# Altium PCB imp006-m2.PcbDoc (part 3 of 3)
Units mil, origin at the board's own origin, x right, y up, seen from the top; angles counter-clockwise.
Board outline 1181.1 x 1515.75 mil, 4 copper layers (Top Layer, Signal Layer 1, Signal Layer 2, Bottom Layer), stack 31.759 mil thick; 78 components, 116 nets, 508 pads, 482 vias.
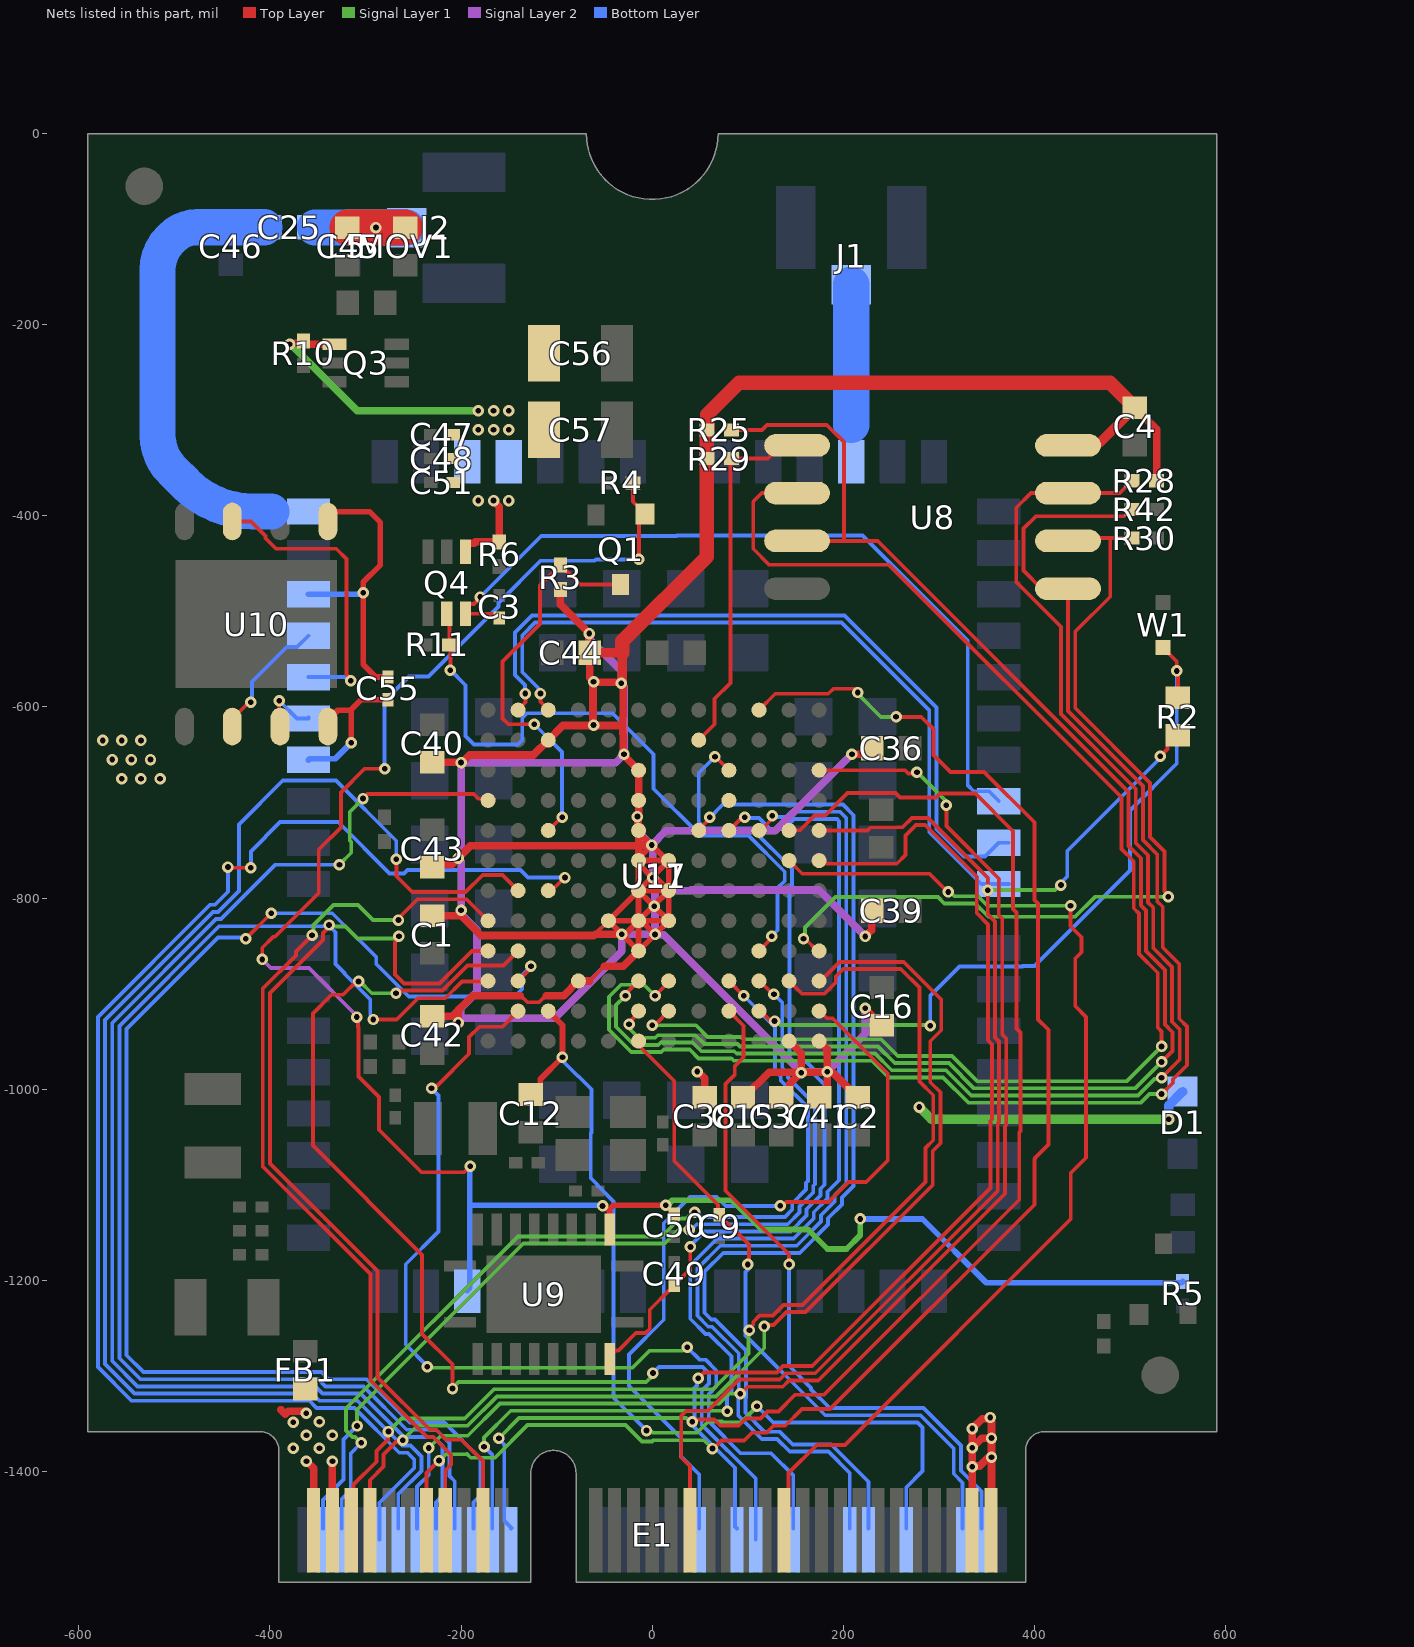
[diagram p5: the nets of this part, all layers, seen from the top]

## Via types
v1: diameter 12, hole 6, Top Layer to Bottom Layer, tented both sides, 300 vias
v2: diameter 16, hole 8, Top Layer to Bottom Layer, tented both sides, 95 vias
v3: diameter 12, hole 6, Top Layer to Signal Layer 1, tented both sides, 86 vias
v4: diameter 141.73, hole 137.8, Top Layer to Bottom Layer, tented both sides, 1 vias

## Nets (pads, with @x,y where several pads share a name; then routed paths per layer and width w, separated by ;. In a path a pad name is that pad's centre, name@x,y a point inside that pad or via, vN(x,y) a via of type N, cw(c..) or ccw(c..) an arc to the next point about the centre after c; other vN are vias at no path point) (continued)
PINW: E1.73 U17.J2 | length 724.1
  Top Layer w4: U17.J2@80.2,-918.19 95.6,-933.59 95.6,-966.46 86.43,-975.63 86.43,-984.69 79.69,-991.43 76.7,-994.41 76.7,-1106.17 143.19,-1172.65 v1(143.19,-1183.26)
  Bottom Layer w4: v1(143.19,-1183.26) 143.19,-1289.37 166.27,-1312.46 166.27,-1314.18 185.78,-1333.69 283.9,-1333.69 322.96,-1372.75 322.96,-1399.22 344.49,-1420.75 E1.73@344.49,-1459.65
PINXA: E1.8 U17.M3 | length 1137.2
  Top Layer w4: E1.8@-295.28,-1449.8 -295.28,-1409.09 -281.04,-1394.86 -281.04,-1382.1 -267.66,-1368.72 -262.53,-1368.72 v3(-261,-1367.19) ; v3(117.16,-1248.19) 118.69,-1246.66 126.96,-1246.66 140.42,-1233.19 160.35,-1233.19 293.5,-1100.04 293.5,-1064.43 301.5,-1056.43 301.5,-1003.19 290.96,-992.65 290.96,-949.84 302.5,-938.3 302.5,-906.05 263.14,-866.69 196.03,-866.69 176.03,-886.69 U17.M3@174.69,-886.69
  Signal Layer 1 w4: v3(-261,-1367.19) -245.93,-1352.11 -193.15,-1352.11 -162.49,-1321.46 66.77,-1321.46 117.16,-1271.06 v3(117.16,-1248.19)
PINXB: E1.6 U17.L3 | length 1171.6
  Top Layer w4: E1.6@-314.96,-1449.8 -314.96,-1428.34 -312.49,-1425.87 -312.49,-1413.67 -288.54,-1389.72 -288.54,-1378.47 -276.62,-1366.54 -276.62,-1358.81 v3(-276,-1358.19) ; v3(101.66,-1252.19) 101.66,-1250.02 105.66,-1246.02 105.66,-1243.43 112.4,-1236.69 126.32,-1236.69 137.32,-1225.69 157.24,-1225.69 286,-1096.93 286,-1061.32 294,-1053.32 294,-1006.3 279.5,-991.8 279.5,-893.66 260.03,-874.19 199.8,-874.19 192.07,-881.93 192.07,-888.23 180.22,-900.07 156.56,-900.07 U17.L3@143.19,-886.69
  Signal Layer 1 w4: v3(-276,-1358.19) -262.43,-1344.61 -196.25,-1344.61 -165.6,-1313.96 63.66,-1313.96 100.9,-1276.72 100.9,-1252.95 v3(101.66,-1252.19)
PINXC: E1.3 U17.K3 | length 961.9
  Top Layer w4: U17.K3@111.69,-886.69 112.54,-886.69 126.49,-900.65 v1(127.34,-900.65)
  Signal Layer 1 w4: v1(-308.9,-1352.36) -308.9,-1335.36 -135,-1161.46 13.1,-1161.46 27.7,-1146.86 v1(38.83,-1146.86)
  Bottom Layer w4: E1.3@-344.49,-1459.65 -344.49,-1429.72 -323.04,-1408.27 -323.04,-1366.5 v1(-308.9,-1352.36) ; v1(38.83,-1146.86) 40.99,-1146.86 46.66,-1141.19 141.87,-1141.19 154,-1129.06 154,-1122.51 168.5,-1108.01 168.5,-1101 170.47,-1099.03 170.47,-1016.06 142.03,-987.62 142.03,-983.48 136.09,-977.54 136.09,-969.79 136.09,-909.36 v1(127.34,-900.65)
PINXD: E1.5 U17.J3 | length 979.6
  Top Layer w4: U17.J3@80.2,-886.69 95.62,-902.12 v1(95.71,-902.12)
  Signal Layer 1 w4: v1(-304.53,-1369.96) -304.77,-1369.96 -310.87,-1363.86 -313.66,-1363.86 -320.4,-1357.12 -320.4,-1333.86 -140.5,-1153.96 9.99,-1153.96 28.59,-1135.36 35.93,-1135.36 42.6,-1128.69 v1(44.3,-1128.69)
  Bottom Layer w4: E1.5@-324.8,-1459.65 -324.8,-1428.46 -315.54,-1419.2 -315.54,-1380.97 v1(-304.53,-1369.96) ; v1@45.11,-1127.88 50.92,-1133.69 138.76,-1133.69 146.5,-1125.95 146.5,-1119.41 161,-1104.91 161,-1097.89 162.97,-1095.92 162.97,-1019.17 134.53,-990.73 134.53,-986.58 128.59,-980.64 128.59,-935 v1(95.71,-902.12)
PinXE: E1.9 U17.C6 | length 1485.3
  Top Layer w4: v1(-443.95,-767.5) -443.25,-768.19 v1(-420,-768.19) ; U17.C6@-108.78,-792.2 -105.6,-792.2 -101.57,-788.17 -101.19,-788.17 -91.51,-778.5 v1(-91.39,-778.5)
  Bottom Layer w4: v1(-443.95,-767.5) -443.95,-793.4 -457.53,-806.98 -462.59,-806.98 -580,-924.39 -580,-1290.73 -544.73,-1326 -358.65,-1326 -351.15,-1333.5 -311.49,-1333.5 -264.66,-1380.34 -256.16,-1380.34 -249.04,-1387.45 -249.04,-1396.22 -285.43,-1432.61 E1.9@-285.43,-1471.46 ; v1(-420,-768.19) -420,-751.04 -389.44,-720.48 -328.48,-720.48 -274.77,-774.19 -259.74,-774.19 -256.23,-770.68 -137.69,-770.68 -129.97,-778.41 -91.48,-778.41 v1(-91.39,-778.5)
PinXF: E1.11 U17.B6 | length 1477.4
  Top Layer w4: v1(-267.84,-759.35) -267.61,-759.59 -267.61,-777.18 -251.09,-793.69 -195.25,-793.69 -177.31,-775.75 -156.73,-775.75 U17.B6@-140.28,-792.2
  Bottom Layer w4: v1(-267.84,-759.35) -267.84,-740.03 -330.87,-677.01 -386.55,-677.01 -432.45,-722.91 -432.45,-792.51 -454.42,-814.48 -459.48,-814.48 -572.5,-927.5 -572.5,-1287.62 -541.62,-1318.5 -355.55,-1318.5 -348.05,-1326 -308.39,-1326 -261.55,-1372.84 -253.05,-1372.84 -241.54,-1384.34 -241.54,-1399.33 -265.75,-1423.53 E1.11@-265.75,-1459.65
PinXG: E1.13 U17.M10 | length 1384.9
  Top Layer w4: v3(92.24,-1318.69) 99.67,-1311.26 136.6,-1311.26 143.17,-1304.69 173.7,-1304.69 369,-1109.39 369,-1039.11 370.5,-1037.61 370.5,-946.79 366.29,-942.58 366.29,-821.31 362.5,-817.52 362.5,-779.18 307.75,-724.43 v3(307.75,-702.8) ; U17.M10@174.69,-666.22 264.33,-666.22 267.87,-669.76 270.66,-669.76 270.7,-669.72 275.47,-669.72 v3(277,-668.19)
  Signal Layer 1 w4: v1(-233.83,-1375.35) -221.02,-1362.54 -192.96,-1362.54 -159.38,-1328.96 69.88,-1328.96 80.14,-1318.69 89.24,-1318.69 v3@89.66,-1319.1 ; v3(277,-668.19) 306.22,-697.41 306.22,-701.27 v3(307.75,-702.8)
  Bottom Layer w4: E1.13@-246.06,-1459.65 -246.06,-1415.77 -233.88,-1403.59 -233.88,-1375.4 v1(-233.83,-1375.35)
PinXH: E1.15 U17.A9 | length 1352.7
  Top Layer w4: v3(-302.64,-695.87) -305.05,-693.47 -300.73,-693.47 -298.26,-691 -186.8,-691 -181.74,-696.06 -173.43,-696.06 U17.A9@-171.77,-697.72
  Signal Layer 1 w4: v1(-327.3,-765) -314.89,-752.59 -314.89,-741.38 -316.5,-739.76 -316.5,-709.73 v3(-302.64,-695.87)
  Bottom Layer w4: v1(-327.3,-765) -394.33,-765 -451.31,-821.98 -456.37,-821.98 -565,-930.61 -565,-1284.52 -538.52,-1311 -352.44,-1311 -344.94,-1318.5 -305.28,-1318.5 -259.92,-1363.85 -229.07,-1363.85 -219.54,-1373.38 -219.54,-1425.25 -226.38,-1432.09 E1.15@-226.38,-1459.65
PinXJ: E1.52 U17.L7 | length 1116.5
  Top Layer w4: E1.52@137.8,-1449.8 142.69,-1444.91 142.69,-1401.63 172.13,-1372.19 201.66,-1372.19 438,-1135.85 438,-1087.62 454,-1071.62 454,-924.23 442.7,-912.92 442.7,-863.21 449.29,-856.62 449.29,-840.88 437.79,-829.38 v3(437.79,-807.95) ; U17.L7@143.19,-760.71 157.02,-774.54 290.3,-774.54 309.23,-793.48 v3(309.8,-793.48)
  Signal Layer 1 w4: v3(309.8,-793.48) 311.61,-793.48 316.14,-798.01 340.88,-798.01 350.82,-807.95 v3(437.79,-807.95)
PinXK: E1.47 U17.M7 | length 1116.2
  Top Layer w4: v1(48.03,-1302.33) 48.27,-1302.33 54.34,-1296.26 130.39,-1296.26 136.96,-1289.69 167.49,-1289.69 354,-1103.18 354,-1032.89 355.5,-1031.39 355.5,-953 351.29,-948.79 351.29,-827.52 339.5,-815.73 339.5,-777.39 285.61,-723.5 276.03,-723.5 265.16,-734.38 265.16,-754.8 255.91,-764.05 182.9,-764.05 181.8,-762.96 176.93,-762.96 U17.M7@174.69,-760.71
  Bottom Layer w4: v1(48.03,-1302.33) 47.86,-1302.33 46.81,-1303.38 46.81,-1310.08 44.22,-1312.67 44.22,-1353.79 86.46,-1396.03 86.46,-1457.52 E1.47@88.58,-1459.65
PinXL: U17.J9
PinXN: E1.43 U17.M2 | length 824.4
  Top Layer w4: v1(134,-1122) 135.98,-1122 136.98,-1121 137.16,-1121.19 140.43,-1117.92 184.58,-1117.92 205.4,-1097.1 223.97,-1097.1 246.52,-1074.55 246.52,-983.56 188.66,-925.71 182.9,-925.71 175.38,-918.19 U17.M2@174.69,-918.19
  Bottom Layer w4: E1.43@49.21,-1459.65 49.21,-1403.2 30.28,-1384.27 30.28,-1364.94 -24.29,-1310.38 -24.29,-1277.49 12.05,-1241.15 12.05,-1140.18 39.58,-1112.65 67.55,-1112.65 76.9,-1122 v1(134,-1122)
PinXP: E1.49 U17.B4 | length 1188
  Top Layer w4: v3(-307.33,-887.2) -309.5,-887.2 -323.42,-901.12 -335.43,-901.12 -355,-920.69 -355,-1059 -240.75,-1173.25 -240.75,-1256.06 -209,-1287.81 v3(-209,-1313.19) ; v3(-268.11,-899.56) -265.24,-896.69 -219.5,-896.69 -193.27,-870.46 -155.54,-870.46 U17.B4@-140.28,-855.2
  Signal Layer 1 w4: v3(-307.33,-887.2) -305.91,-887.2 -293.55,-899.56 v3(-268.11,-899.56) ; v3(-209,-1313.19) -209,-1312.8 -202.66,-1306.46 -6.27,-1306.46 0.74,-1299.45 v1(0.74,-1297.02)
  Bottom Layer w4: v1(0.74,-1297.02) 7.08,-1290.69 52.76,-1290.69 59.53,-1297.46 59.53,-1307.97 51.72,-1315.77 51.72,-1350.69 108.27,-1407.23 E1.49@108.27,-1471.46
PinXQ: E1.19 U17.B3 | length 1390.1
  Top Layer w4: v1(-425.42,-842.6) v1(-398.62,-815.81) ; U17.B3@-140.28,-886.69 -127.24,-873.66 -127.24,-871.65 v1(-126.89,-871.29)
  Bottom Layer w4: v1(-425.42,-842.6) -426.82,-841.19 -454.37,-841.19 -550,-936.82 -550,-1278.3 -532.3,-1296 -346.23,-1296 -338.73,-1303.5 -299.07,-1303.5 -253.71,-1348.85 -217.44,-1348.85 -179.71,-1386.59 -179.71,-1424.85 -182.06,-1427.2 -182.12,-1427.2 -187.01,-1432.09 E1.19@-187.01,-1459.65 ; v1(-398.62,-815.81) -334.79,-815.81 -288.85,-861.74 -288.85,-868.89 -254.76,-902.98 -143.91,-902.98 -136.27,-895.35 -136.27,-880.68 v1(-126.89,-871.29)
PinXR: E1.17 U17.A3 | length 1337.9
  Top Layer w4: v1(-292.04,-927) -267.31,-927 -245.02,-904.7 -216.51,-904.7 -199,-887.19 -172.27,-887.19 U17.A3@-171.77,-886.69
  Bottom Layer w4: v1(-292.04,-927) -292.04,-924.84 -295,-921.88 -295,-906.13 -322,-879.13 -322,-878.48 -331.5,-868.98 -331.5,-835.66 -337.68,-829.48 -453.27,-829.48 -557.5,-933.71 -557.5,-1281.41 -535.41,-1303.5 -349.33,-1303.5 -341.83,-1311 -302.17,-1311 -256.82,-1356.35 -225.96,-1356.35 -212.04,-1370.28 -212.04,-1404.77 -206.69,-1410.12 E1.17@-206.69,-1459.65
PinXS: E1.53 U17.B2 | length 998.1
  Top Layer w4: v1(-230.91,-998.97) -228.74,-998.97 -225.82,-996.05 -224.86,-996.05 -191.68,-962.87 -191.68,-945.32 -180.89,-934.53 -156.62,-934.53 U17.B2@-140.28,-918.19
  Signal Layer 1 w4: v1(-235.54,-1290.38) -234.46,-1291.46 -20.57,-1291.46 -2.65,-1273.54 32.01,-1273.54 35.51,-1270.04 v1(36.71,-1270.04)
  Bottom Layer w4: v1(-235.54,-1290.38) -235.54,-1289.59 -257.87,-1267.25 -257.87,-1183.06 -223.5,-1148.69 -223.5,-1006.38 v1(-230.91,-998.97) ; v1(36.71,-1270.04) 49.63,-1282.96 55.64,-1282.96 67.03,-1294.35 67.03,-1311.07 59.22,-1318.88 59.22,-1347.58 92.61,-1380.96 124.49,-1380.96 147.64,-1404.11 E1.53@147.64,-1459.65
PinXT: E1.23 U17.L8 | length 1409.2
  Top Layer w4: 48.34,-1345.69 64.97,-1345.69 71.24,-1351.96 90.58,-1351.96 98.06,-1344.48 113.19,-1344.48 120.61,-1337.07 132.01,-1337.07 149.38,-1319.69 179.91,-1319.69 384,-1115.6 384,-1045.32 385.5,-1043.82 385.5,-940.58 381.29,-936.37 381.29,-815.09 377.5,-811.3 377.5,-729.99 338.2,-690.69 301.24,-690.69 297.24,-694.69 259.27,-694.69 254.64,-690.06 204.39,-690.06 181,-713.46 169.97,-713.46 154.51,-728.92 143.49,-728.92 U17.L8@143.19,-729.21
  Signal Layer 1 w4: v1(-160.46,-1365.11) -139.3,-1343.96 35.66,-1343.96 39.66,-1347.96 v3(42,-1347.96)
  Bottom Layer w4: v1(-160.46,-1365.11) -160.46,-1365.93 -154.93,-1371.46 -154.93,-1451.41 -147.17,-1459.18 E1.23@-147.64,-1459.65
PinXU: E1.59 U17.K8 | length 1061.6
  Top Layer w4: U17.K8@111.69,-729.21 113.31,-729.21 123.99,-718.53 123.99,-715.29 v1(125.52,-713.76)
  Bottom Layer w4: v1(125.52,-713.76) 127.89,-713.76 129.14,-715 139.95,-715 145.26,-709.69 196.38,-709.69 203.02,-716.33 203.02,-1098.3 191,-1110.32 191,-1117.33 176.5,-1131.83 176.5,-1138.38 151.19,-1163.69 71.19,-1163.69 47.28,-1187.6 47.28,-1237.04 58.69,-1248.46 62.65,-1248.46 90.5,-1276.31 90.5,-1319.43 90.03,-1319.89 90.03,-1341.46 114.54,-1365.96 130.7,-1365.96 143.93,-1379.19 184.26,-1379.19 206.69,-1401.62 E1.59@206.69,-1459.65
PinXV: E1.21 U17.J8 | length 1239.5
  Top Layer w4: U17.J8@80.2,-729.21 v1@91.74,-717.67
  Signal Layer 1 w4: v1(-176,-1374.04) -176,-1364.39 -148.07,-1336.46 76.45,-1336.46 76.86,-1336.87 v1(78.53,-1336.87)
  Bottom Layer w4: v1@-174.47,-1375.57 -167.32,-1382.71 E1.21@-167.32,-1459.65 ; v1(78.53,-1336.87) 78.22,-1336.57 78.22,-1321.09 83,-1316.32 83,-1279.41 59.54,-1255.96 55.58,-1255.96 39.78,-1240.15 39.78,-1184.5 68.08,-1156.19 148.08,-1156.19 169,-1135.27 169,-1128.73 183.5,-1114.23 183.5,-1107.21 195.52,-1095.19 195.52,-719.54 193.18,-717.19 148.37,-717.19 137.88,-727.69 123.19,-727.69 111.69,-716.19 97.42,-716.19 v1(96.7,-715.47)
PinXW: E1.61 U17.H8 | length 1143.6
  Top Layer w4: U17.H8@48.7,-729.21 48.7,-728.11 60.23,-716.57 v1(60.23,-715.47)
  Bottom Layer w4: v1(60.23,-715.47) 60.48,-715.47 73.75,-702.19 199.49,-702.19 210.52,-713.22 210.52,-1101.41 198.5,-1113.43 198.5,-1120.44 184,-1134.94 184,-1141.49 154.3,-1171.19 74.3,-1171.19 54.78,-1190.71 54.78,-1233.94 61.79,-1240.96 65.75,-1240.96 98,-1273.2 98,-1322.54 97.53,-1323 97.53,-1338.35 117.65,-1358.46 133.81,-1358.46 147.03,-1371.69 187.37,-1371.69 226.38,-1410.7 E1.61@226.38,-1459.65
PinYA: E1.20 U17.A4 | length 989.4
  Top Layer w4: v3(-338.14,-828.12) -338.14,-830.29 -344.46,-836.61 -344.46,-843.72 -400,-899.26 -400,-1077.79 -287.43,-1190.35 -287.43,-1301.45 -232.52,-1356.35 -225.96,-1356.35 -215.63,-1366.69 -199.61,-1366.69 -177.17,-1389.13 E1.20@-177.17,-1449.8 ; v3(-265,-840) -265,-842.16 -269,-846.16 -269,-879.86 -259.67,-889.19 -222.61,-889.19 -188.61,-855.2 U17.A4@-171.77,-855.2
  Signal Layer 1 w4: v3(-338.14,-828.12) -336.72,-829.53 -321.06,-829.53 -308.41,-842.19 -269.35,-842.19 -267.16,-840 v3(-265,-840)
PinYB: E1.16 U17.A5 | length 960.8
  Top Layer w4: v3(-355.96,-838.95) -372.91,-855.9 -372.91,-859.88 -407.5,-894.47 -407.5,-1080.89 -294.93,-1193.46 -294.93,-1304.55 -235.63,-1363.85 -229.07,-1363.85 -210.5,-1382.43 -210.5,-1392.95 -216.54,-1398.99 E1.16@-216.54,-1461.61 ; v3(-265.54,-823) -265.54,-821.02 -245.71,-801.19 -194.28,-801.19 U17.A5@-171.77,-823.7
  Signal Layer 1 w4: v3(-355.96,-838.95) -354.43,-837.42 -354.43,-828.15 -333.48,-807.19 -307.92,-807.19 -292.11,-823 v3(-265.54,-823)
PinYC: E1.42 R2.2 U17.M8 | length 1368.5
  Top Layer w4: E1.42@39.37,-1449.8 39.37,-1394.17 30.28,-1385.08 30.28,-1341.91 35.73,-1336.46 58.21,-1336.46 90.91,-1303.76 133.5,-1303.76 140.06,-1297.19 170.59,-1297.19 361.5,-1106.28 361.5,-1036 363,-1034.5 363,-949.9 358.79,-945.69 358.79,-824.41 351,-816.62 351,-778.28 288.72,-716 271.73,-716 261.88,-725.85 228.72,-725.85 225.36,-729.21 U17.M8@174.69,-729.21 ; v1(531.63,-651.54) 539.2,-643.96 539.2,-639.5 549.02,-629.68 R2.2@550,-629.68
  Signal Layer 1 w4: v3(351,-791.87) 351.39,-791.48 421.29,-791.48 426.47,-786.3 v1(427.63,-786.3)
  Bottom Layer w4: v1(427.63,-786.3) 427.63,-784.13 434.25,-777.51 434.25,-750.76 531.63,-653.38 v1(531.63,-651.54)
PinYD: E1.14 U17.K12 | length 1619
  Top Layer w4: E1.14@-236.22,-1461.61 -236.22,-1401.62 v3(-223.1,-1388.5) ; v3@63,-1376.97 v3(63,-1376) ; v3@63.03,-1377 72.63,-1367.39 96.36,-1367.39 104.27,-1359.48 119.41,-1359.48 126.82,-1352.07 139.22,-1352.07 156.6,-1334.69 186.13,-1334.69 400,-1120.82 400,-1073.19 400.5,-1072.69 400.5,-1072.08 405.2,-1067.39 405.2,-1067.26 414.5,-1057.95 414.5,-937.76 403.79,-927.05 403.79,-805.77 400,-801.98 400,-720.67 347.28,-667.96 312.02,-667.96 294.32,-650.25 294.32,-623.18 281.46,-610.33 v3(255.16,-610.33) ; U17.K12@111.69,-603.23 128.73,-586.19 184.23,-586.19 189.57,-580.85 v3@212.76,-580.85
  Signal Layer 1 w4: v3(-223.1,-1388.5) -222.79,-1388.19 -222,-1388.19 -215.77,-1381.96 -193.97,-1381.96 -193.72,-1381.71 -189.9,-1385.54 -164.62,-1385.54 -130.54,-1351.46 -28,-1351.46 -10.76,-1368.69 -0.06,-1368.69 1.44,-1367.19 53.94,-1367.19 62.75,-1376 v3(63,-1376) ; v3(215.16,-584.85) 215.16,-586.37 239.12,-610.33 v3(255.16,-610.33)
PinYK: Q1.3 R3.2 U17.C8 | length 423.1
  Top Layer w4: v1(-123.39,-618.11) -150.5,-618.11 -156.73,-611.88 -156.73,-552.48 -117.5,-513.25 -117.5,-472.66 -101.97,-457.13 -100.99,-457.13 R3.2@-96.1,-452.24 ; U17.C8@-108.78,-729.21 -95.01,-715.44 v1(-94.26,-715.44) ; R3.2@-96.1,-451.26 R3.2@-96.1,-452.24 ; Q1.3@-33.03,-471.87 -75.48,-471.87 -90.23,-457.13 -91.21,-457.13 R3.2@-96.1,-452.24
  Bottom Layer w4: v1(-123.39,-618.11) -94.26,-647.24 v1(-94.26,-715.44)
QSPI_CLK: R30.1 U8.6 U17.M4 | length 943.8
  Top Layer w4: v3(158.29,-842.48) 160.13,-842.48 172.84,-855.2 U17.M4@174.69,-855.2 ; U8.6@435.04,-426.22 438.07,-423.19 479.19,-423.19 ; R30.1@502.2,-423.19 479.19,-423.19 ; v3(540,-798.65) 540,-796.49 536,-792.49 536,-751.09 521,-736.09 521,-679.49 442.7,-601.18 442.7,-521.17 479.19,-484.68 479.19,-423.19
  Signal Layer 1 w4: v3(158.29,-842.48) 159.82,-840.95 159.82,-836 159.89,-835.92 159.89,-830.69 191.6,-798.98 299.03,-798.98 305.57,-805.51 337.77,-805.51 351.72,-819.45 442.55,-819.45 463.35,-798.65 v3(540,-798.65)
QSPI_CS: R29.2 U8.1 U17.H11 | length 384.1
  Top Layer w4: U17.H11@48.7,-634.72 65.31,-618.11 65.31,-591.33 81.81,-574.83 81.81,-340 120.84,-340 125.18,-335.66 125.18,-335.28 134.25,-326.22 U8.1@151.57,-326.22
QSPI_IO0: R42.1 U8.5 U17.G3 | length 1541.9
  Top Layer w4: v3(3,-902.19) 17.2,-887.98 U17.G3@17.2,-886.69 ; R42.1@496.33,-398.12 493.99,-400.46 401.39,-400.46 388.46,-413.39 388.46,-457.33 407.35,-476.22 U8.5@435.04,-476.22 435.2,-476.38 435.2,-604.29 513.5,-682.6 513.5,-739.19 528.5,-754.19 528.5,-803.42 534.14,-809.06 534.14,-851.49 551.5,-868.84 551.5,-926.2 559.5,-934.2 559.5,-974.86 544.63,-989.72 544.63,-993.37 v3(533,-1005) ; R42.1@496.33,-398.08 501.22,-393.19 R42.1@502.2,-393.19
  Signal Layer 1 w4: v3(3,-902.19) -8.57,-890.62 -32.76,-890.62 -45.32,-903.18 -45.32,-937.77 -21.96,-961.12 9.42,-961.12 12.05,-958.5 39.23,-958.5 48.42,-967.69 82.76,-967.69 85.26,-970.19 230.14,-970.19 247.58,-987.62 304.23,-987.62 330.64,-1014.03 511.37,-1014.03 520.4,-1005 v3(533,-1005)
QSPI_IO1: U8.2 U17.G2 | length 1461.2
  Top Layer w4: v3@3.85,-931.54 U17.G2@17.2,-918.19 ; U8.2@151.57,-376.22 114.59,-376.22 105.66,-385.15 105.66,-434.41 122.51,-451.26 247.82,-451.26 491,-694.43 491,-748.51 503.91,-761.43 503.91,-810.65 509.29,-816.03 509.29,-858.45 529,-878.16 529,-935.52 533,-939.52 v3(533,-955.19)
  Signal Layer 1 w4: v3(0,-933.07) 45.62,-933.07 57.74,-945.19 92.42,-945.19 94.92,-947.69 239.46,-947.69 256.9,-965.12 313.55,-965.12 339.96,-991.53 496.66,-991.53 v3(533,-955.19)
QSPI_IO2: R25.2 U8.3 U17.F2 | length 1612.1
  Top Layer w4: v3(-24.21,-932) -24.21,-930.06 -14.29,-920.13 U17.F2@-14.29,-918.19 ; R25.2@82.8,-310 115,-310 120,-305 182.69,-305 200.5,-322.81 200.5,-425.25 199.53,-426.22 ; U8.3@151.57,-426.22 199.53,-426.22 ; v3(533,-971.45) 544.5,-959.95 544.5,-940.41 536.5,-932.41 536.5,-875.06 516.79,-855.35 516.79,-812.92 511.41,-807.54 511.41,-758.32 498.5,-745.41 498.5,-688.81 235.91,-426.22 199.53,-426.22
  Signal Layer 1 w4: v3(-24.21,-932) -22.68,-933.53 -22.68,-937.74 -14.3,-946.12 3.21,-946.12 5.83,-943.5 45.44,-943.5 54.63,-952.69 89.32,-952.69 91.82,-955.19 236.36,-955.19 253.79,-972.62 310.44,-972.62 336.85,-999.03 505.16,-999.03 532.74,-971.45 v3(533,-971.45)
QSPI_IO3: R28.2 U8.7 U17.F3 | length 1475.6
  Top Layer w4: v3(-28,-902.12) -28,-900.4 U17.F3@-14.29,-886.69 ; R28.2@502.2,-363.19 501.22,-363.19 496.33,-368.08 496.33,-369.06 489.17,-376.22 U8.7@435.04,-376.22 396.19,-376.22 380.96,-391.46 380.96,-469.26 427.7,-516 427.7,-607.4 506,-685.7 506,-742.3 518.91,-755.21 518.91,-804.44 524.29,-809.81 524.29,-852.24 544,-871.95 544,-929.31 552,-937.31 552,-969 534.69,-986.31 v3@534.69,-987.32
  Signal Layer 1 w4: v3(-28,-902.12) -37.82,-911.94 -37.82,-934.66 -18.86,-953.62 6.32,-953.62 8.94,-951 42.33,-951 51.52,-960.19 85.87,-960.19 88.37,-962.69 233.25,-962.69 250.68,-980.12 307.34,-980.12 333.74,-1006.53 508.26,-1006.53 525.41,-989.38 531.62,-989.38 v3(533,-988)
R_USB_N: U11.10 U17.C12 | length 792.7
  Top Layer w4: v1(-117,-586) -117,-594.44 -108.78,-602.66 U17.C12@-108.78,-603.23
  Bottom Layer w4: v1(-117,-586) -117,-583.53 -116.43,-582.96 -136.04,-563.35 -136.04,-525.06 -122.67,-511.69 198.08,-511.69 289.96,-603.56 289.96,-731.02 344.22,-785.28 U11.10@362.67,-785.28 U11.10@373.22,-785.28
R_USB_P: U11.9 U17.B12 | length 798
  Top Layer w4: U17.B12@-140.28,-602.66 -132.62,-595.01 v1@-132.62,-585.46
  Bottom Layer w4: v1(-133,-586) -133,-577 -143.54,-566.46 -143.54,-521.96 -125.78,-504.19 201.19,-504.19 297.46,-600.46 297.46,-727.91 326,-756.46 348.19,-756.46 U11.9@362.67,-741.97 U11.9@373.13,-741.97
RADIO_VUSB: Q4.2 R11.1 U17.K4 | length 684.4
  Top Layer w4: Q4.2@-215,-502.48 -212.2,-505.28 R11.1@-212.2,-535 -211.23,-535.97 v1(-211.23,-561.45) ; U17.K4@111.69,-855.2 125,-841.89 v1(125,-840)
  Bottom Layer w4: v1(-211.23,-561.45) -195.43,-577.25 -195.43,-630.27 -186.51,-639.19 -140.72,-639.19 -136.04,-634.51 -136.04,-611.74 -130.87,-606.57 -41.43,-606.57 1.46,-649.46 1.46,-685.54 50.39,-734.47 100.81,-734.47 138.73,-772.39 138.73,-781.92 131.23,-789.42 131.23,-833.66 125,-839.89 v1(125,-840)
RESCUE: R2.1 U17.K2 W1.1 | length 767.6
  Top Layer w4: U17.K2@111.69,-918.19 113.38,-918.19 122.34,-927.16 126.47,-927.16 v3(128,-928.69) ; W1.1@535,-538.62 548.9,-552.52 v1(548.9,-562.25) 550,-563.35 R2.1@550,-590.32
  Signal Layer 1 w4: v3(128,-928.69) 130.16,-928.69 134.16,-932.69 290.15,-932.69 v1(291,-933.53)
  Bottom Layer w4: v1(291,-933.53) 291,-901.87 321.39,-871.48 387.59,-871.48 387.88,-871.19 400,-871.19 500,-771.19 500,-708.19 548.9,-659.29 v1(548.9,-562.25)
RESET_L: C9.2 E1.71 U17.F1 | length 710.3
  Top Layer w4: U17.F1@-14.29,-949.68 -14.29,-953.97 23,-991.26 23,-1074.97 68.86,-1120.83 68.86,-1130.24 C9.2@70,-1131.38 70,-1132.36 73.91,-1136.27 74.89,-1136.27 101.2,-1162.58 v1@101.2,-1183.26
  Bottom Layer w4: v1@102.71,-1186.09 97.5,-1191.29 97.5,-1257.62 181.07,-1341.19 280.79,-1341.19 315.46,-1375.85 315.46,-1402.33 324.8,-1411.67 E1.71@324.8,-1459.65
  other v1: 99.88,-1183.26
RF_1_ANT: J1.2 U11.60 | length 147.3
  Bottom Layer w37.8: 208.27,-305.12 J1.2@208.27,-157.85
RF_2: C25.2 C46.2 U11.49 | length 468.5
  Bottom Layer w37.76: C25.2@-406,-98 C46.2@-441,-98 -476.06,-98 ccw(c-476.06,-135.41) -502.51,-108.96 -504.62,-111.07 ccw(c-473.52,-142.16) -517.5,-142.16 -517.5,-315.95 ccw(c-466.29,-315.95) -502.51,-352.15 -488.44,-366.22 ccw(c-417.73,-295.51) -417.73,-395.51 -398.7,-395.51 -398.62,-395.59
RF_2_ANT: C25.1 C45.2 J2.2 L5.2 MOV1.2 | length 156.6
  Top Layer w37.76: L5.2@-319,-98.32 v1(-289.13,-98.32) MOV1.2@-258.56,-98.32
  Bottom Layer w37.76: C25.1@-353,-98.43 J2.2@-256.89,-98.43
SIM_CLK: U10.6 U11.46 | length 135.6
  Top Layer w4: U10.6@-439.43,-620.46 -439.43,-612.39 -422.04,-595 v1(-420,-595)
  Bottom Layer w4: v1(-420,-595) -418.78,-593.78 -418.78,-573.6 -382.39,-537.21 -371.55,-537.21 U11.46@-359.77,-525.43
SIM_GND: C55.1 U10.1 U11.47 | length 312
  Top Layer w6: U10.1@-339.11,-405.89 U10.1@-339.43,-405.89 -339.43,-401.91 -333.11,-395.59 -295.92,-395.59 -284.47,-407.04 -284.47,-451.31 -302.43,-469.27 v1(-302.43,-480.46) -302.43,-555.61 -289.31,-568.73 C55.1@-276.5,-568.73
  Bottom Layer w6: U11.47@-359.77,-482.13 -304.1,-482.13 v1(-302.43,-480.46)
SIM_IO: U10.3 U11.45 | length 329.7
  Top Layer w4: U10.3@-439.43,-423.37 U10.3@-439.43,-405.89 -420.02,-405.89 -404.78,-421.13 -404.78,-423.49 -393.86,-434.41 -330.59,-434.41 -320,-445 -320,-566.11 -315.47,-570.65 v1(-315.47,-572.46)
  Bottom Layer w4: U11.45@-359.77,-568.74 -321.35,-568.74 -317.63,-572.46 v1(-315.47,-572.46)
SIM_RST: U10.7 U11.44 | length 65.6
  Top Layer w4: v1(-390.3,-593.46) -390.3,-619.59 U10.7@-389.43,-620.46
  Bottom Layer w4: v1(-390.3,-593.46) -371.71,-612.05 U11.44@-359.77,-612.05
V_BUFF: C49.2 U9.19 U17.J10 | length 907.2
  Top Layer w4: U9.19@-44.65,-1282.37 -44.65,-1276.71 -41.13,-1273.2 -35.48,-1273.2 -17.27,-1255 -6.93,-1255 -2.65,-1250.72 -2.65,-1230.65 18.11,-1209.89 19.09,-1209.89 23,-1205.98 C49.2@23,-1205 23,-1204.02 26.91,-1200.11 27.89,-1200.11 39.78,-1188.22 39.78,-1165.22 v1(40,-1165) ; v1(65.65,-652.01) 66.6,-652.97 66.94,-652.97 U17.J10@80.2,-666.22
  Bottom Layer w4: v1(40,-1165) 40,-1163.46 54.77,-1148.69 144.98,-1148.69 161.5,-1132.17 161.5,-1125.62 176,-1111.12 176,-1104.11 180.17,-1099.94 180.17,-995.12 170.47,-985.42 170.47,-980.39 161.43,-971.35 148.25,-971.35 143.59,-966.69 143.59,-788.9 146.23,-786.26 146.23,-769.28 103.92,-726.97 55.23,-726.97 48.73,-720.48 48.73,-668.92 v1(65.65,-652.01)
V_INT: C50.2 Q1.1 R4.1 R5.1 U9.2 U11.29 | length 2092.7
  Top Layer w4: v1(-408.02,-864.14) -408.02,-851.86 -396.67,-840.51 -394.99,-840.51 -349,-794.52 -349,-749.3 -325.65,-725.95 -325.65,-689.35 -300.96,-664.66 v1(-280,-664.66) ; v1(-309.28,-924.45) -307.75,-925.98 -307.75,-935.05 -307.39,-935.41 -307.39,-986.74 -286,-1008.13 -286,-1042.36 -241.55,-1086.81 -196.84,-1086.81 v1(-190.5,-1080.5) ; R4.1@-20.25,-365.46 -20.25,-385.24 -16.26,-389.23 -15.28,-389.23 -7.44,-397.07 Q1.1@-7.44,-398.06 -13.76,-404.38 v1@-13.76,-445.52
  Top Layer w6: -46.73,-1125.67 -44.65,-1125.67 ; U9.2@-44.65,-1146.54 -44.65,-1125.67 ; v3(14.08,-1121.46) -40.43,-1121.46 -44.65,-1125.67
  Signal Layer 2 w4: v1(-408.02,-864.14) -399.13,-873.03 -359.3,-873.03 -309.28,-923.05 v1(-309.28,-924.45)
  Signal Layer 1 w6: v3(14.08,-1121.46) 15.64,-1121.46 20.91,-1116.19 83.83,-1116.19 114.5,-1146.86 163.07,-1146.86 183.48,-1167.27 203.24,-1167.27 217.72,-1152.78 v1(217.72,-1135.68)
  Bottom Layer w4: v1(-280,-664.66) -280,-593.58 -254.56,-568.14 -234.19,-568.14 -161,-494.95 -161,-491.13 -116.83,-446.96 -60.11,-446.96 -58.66,-445.52 v1(-14.29,-445.52)
  Bottom Layer w6: U11.29@-193.43,-1210.52 -190.86,-1207.95 -190.86,-1121.46 ; v1(-190.5,-1080.5) -190.86,-1080.87 -190.86,-1121.46 ; v1(-51.93,-1122.09) -52.57,-1121.46 -190.86,-1121.46 ; v1(217.72,-1135.68) 282.67,-1135.68 349.48,-1202.5 553.7,-1202.5 R5.1@555,-1201.2
V_USB: C3.2 Q4.3 U11.8 | length 837.2
  Top Layer w4: v1(-180,-485) -180,-485.92 -186.34,-492.27 -191.41,-492.27 -195.31,-496.17 Q4.3@-195.31,-502.48 -163.91,-502.48 -160,-506.39 C3.2@-160,-506.81
  Bottom Layer w4: v1(-180,-485) -116.13,-421.13 25.43,-421.13 25.99,-420.58 219.88,-420.58 330.24,-530.93 330.24,-682.11 336.38,-688.25 352.26,-688.25 U11.8@362.67,-698.66
VDD: C1.2 C2.2 C4.2 C15.2 C16.2 C36.2 C37.2 C38.2 C39.2 C40.2 C41.2 C42.2 C43.2 C44.2 D1.A E1.72 E1.74 R3.1 R25.1 R28.1 R29.1 U8.8 U17.C11 U17.D3 U17.E5 U17.F4 U17.F5 U17.F6 U17.F7 U17.F8 U17.F9 U17.F10 U17.G5 U17.G6 U17.G7 U17.L1 U17.M1 | length 5814.7
  Top Layer w4: v1(-200,-658.19) -200.31,-657.87 v1@-198.68,-657.87 ; -138,-902 -135.18,-904.82 -134.74,-904.82 -130.59,-908.96 -118.46,-908.96 -114.32,-904.82 -113.82,-904.82 -111,-902 ; -65.62,-886.69 -50.24,-871.32 ; -61.54,-839.46 -59.79,-837.7 U17.E5@-45.79,-823.7 ; U17.F8@-14.29,-730.72 U17.F8@-14.29,-729.21 ; U17.F9@-14.29,-699.85 U17.F9@-14.29,-697.72 ; v1(0.46,-778.66) v1@3.66,-778.66
  Top Layer w6: v1@-200,-818.57 v1(-200,-812.69) ; C44.2@-65.42,-545.21 C44.2@-65,-544.8 ; U17.F8@-14.29,-730.72 v1(-0.54,-744.47) ; v1(0.46,-778.66) v1@-0.15,-778.06 ; v1@3.66,-778.66 U17.G6@17.2,-792.2 ; U17.G7@17.2,-760.71 U17.G7@15.69,-760.71 ; U17.E5@-45.79,-823.7 U17.F5@-14.29,-823.7 ; U17.E5@-45.79,-823.7 v1(-31.79,-837.7) ; U17.E5@-45.79,-823.7 U17.F6@-14.29,-792.2 ; v1(-31.79,-837.7) -28.29,-837.7 U17.F5@-14.29,-823.7 ; v1(-31.79,-837.7) -30.04,-839.45 U17.F4@-14.29,-855.2 ; U17.F4@-14.29,-855.2 U17.F5@-14.29,-823.7 ; U17.F4@-14.29,-855.2 v1(2.95,-837.95) ; U17.F5@-14.29,-823.7 U17.F6@-14.29,-792.2 ; U17.F5@-14.29,-823.7 U17.F5@-11.3,-823.7 ; U17.F5@-14.29,-823.7 v1@1.46,-807.95 ; U17.F6@-14.29,-792.2 U17.F7@-14.29,-763.91 ; U17.F6@-14.29,-792.2 v1@1.46,-807.95 ; U17.F6@-14.29,-792.2 v1@-0.15,-778.06 ; U17.F6@-14.29,-792.2 U17.G6@17.2,-792.2 ; U17.F7@-14.29,-763.91 U17.F7@-14.29,-760.71 ; U17.F7@-14.29,-763.91 v1@-0.15,-778.06 ; U17.F7@-14.29,-760.71 -14.29,-758.22 v1(-0.54,-744.47) ; U17.F7@-14.29,-760.71 U17.G7@15.69,-760.71 ; U17.F5@-11.3,-823.7 U17.G5@17.2,-823.7 ; U17.F5@-11.3,-823.7 v1(2.95,-837.95) ; v1(-0.54,-744.47) U17.G7@15.69,-760.71 ; v1@-0.15,-778.06 16.45,-761.46 17.2,-762.22 U17.G6@17.2,-792.2 ; v1@1.46,-807.95 U17.G5@17.2,-823.7 ; v1@1.46,-807.95 U17.G6@17.2,-792.2 ; v1(2.95,-837.95) U17.G5@17.2,-823.7 ; U17.G5@17.2,-823.7 U17.G6@17.2,-792.2
  Top Layer w8: C42.2@-230,-923.5 -209.37,-923.5 -203,-917.13 ; C1.2@-230,-818.5 -200.07,-818.5 -200,-818.57 -179.49,-839.07 -61.16,-839.07 -59.79,-837.7 v1(-31.79,-837.7) ; C43.2@-230,-767.87 -227.21,-765.08 -209.89,-765.08 v1(-203,-758.19) -190.15,-745.33 -15.04,-745.33 -14.29,-744.59 ; C40.2@-230,-657.87 v1@-200.31,-657.87 ; v1(-203,-930.19) -203,-917.13 ; v1@-198.68,-657.87 -191,-650.19 -124.24,-650.19 U17.C11@-108.78,-634.72 -93.41,-619.35 v1@-62.08,-619.35 ; -138,-902 -138.07,-902.07 -178.14,-902.07 -178.21,-902 -187.87,-902 -203,-917.13 ; -111,-902 -110.93,-902.07 -92.66,-902.07 U17.D3@-77.28,-886.69 -65.62,-886.69 ; R3.1@-96.1,-476.85 -96.1,-492.59 -66,-522.69 v1(-66,-523.19) -66,-543.8 C44.2@-65,-544.8 ; C44.2@-65.41,-545.21 -65.41,-569.27 -60.73,-573.96 -34.73,-573.96 -33.63,-575.06 v1(-32.54,-575.06) -32.54,-576.14 -30.41,-578.27 -30.41,-609.6 -30.91,-610.1 -30.91,-618.46 -30.76,-618.61 -30.76,-628.01 -30.41,-628.36 -30.41,-645.76 -30.31,-645.86 -30.31,-648.69 v1(-29.54,-649.46) ; v1@-62,-572.69 -62,-596.77 -61.91,-596.86 -61.91,-619.18 v1@-62.08,-619.35 ; -50.24,-871.32 -30.41,-871.32 U17.F4@-14.29,-855.2 ; -30.76,-619.35 v1@-62.08,-619.35 ; v1@-30.54,-649.97 U17.F10@-14.29,-666.22 U17.F9@-14.29,-697.72 ; v1(-15.46,-714.63) -14.88,-715.21 -14.88,-728.63 U17.F8@-14.29,-729.21 -14.29,-744.47 ; U17.F7@-14.29,-760.71 -14.29,-744.47 ; v1@-14.29,-714.63 U17.F9@-14.29,-699.85 ; v1(-0.54,-744.47) -14.29,-744.47 ; v1(47.21,-981.5) 47.84,-981.5 55,-988.66 C38.2@55,-1008.5 ; C15.2@95,-1008.5 95.98,-1008.5 122.3,-982.19 155.34,-982.19 v1(156,-982.85) ; C37.2@135,-1008.5 135.98,-1008.5 143.8,-1000.69 143.8,-994.39 v1@156,-982.19 ; U17.L1@143.19,-949.68 156,-962.5 v1@156,-982.19 ; U17.M1@174.69,-949.68 174.69,-949.93 183,-958.25 v1(183,-981.69) ; C41.2@175,-1008.5 175.19,-1008.5 183,-1000.69 v1(183,-981.69) ; v1(208.92,-649.46) 224.05,-649.46 C36.2@230.32,-643.19 ; C2.2@215,-1008.5 214.02,-1008.5 206.2,-1000.69 206.2,-999.71 188.95,-982.45 183.77,-982.45 v1(183,-981.69) ; v1(223,-915.19) 223,-915.87 231.2,-924.08 231.2,-925.06 239.02,-932.87 C16.2@240,-932.87 ; v1(223,-840.05) 229.75,-833.3 229.75,-813.75 C39.2@230.32,-813.19 ; E1.72@334.65,-1449.8 334.46,-1449.61 335,-1449.07 v1(335,-1395) ; v1(353.72,-1343.46) 352.64,-1343.46 351.36,-1344.74 345.26,-1344.74 v1(335,-1355) v1(335,-1375) ; E1.74@354.33,-1461.61 355,-1460.94 v1(355,-1385) ; v1@355,-1344.74 v1(355,-1365) ; C4.2@505,-286.77 505.98,-286.77 513.8,-294.58 513.8,-295.57 527.8,-309.57 R28.1@527.8,-363.19 ; v1@156,-982.19 182.5,-982.19 v1(183,-981.69) ; v1(335,-1395) 335.77,-1394.23 342.69,-1394.23 351.16,-1385.77 354.23,-1385.77 v1(355,-1385) ; v1(335,-1395) v1(335,-1375) ; v1(335,-1375) 345,-1365 v1(355,-1365) ; v1(355,-1385) v1(355,-1365)
  Top Layer w10: C44.2@-65.31,-543.19 -31.31,-543.19 -31.31,-574.91 v1@-32.54,-576.14 ; U8.8@435.04,-326.22 437.65,-323.61 468.16,-323.61 497.2,-294.57 497.2,-293.58 C4.2@504.02,-286.77
  Top Layer w15: -31.31,-543.19 -31.31,-531.31 57.2,-442.8 R29.1@57.2,-340 R25.1@57.2,-310 57.58,-309.63 57.58,-293.92 90.74,-260.76 478.99,-260.76 499.7,-281.48 499.7,-282.46 504.02,-286.77 C4.2@505,-286.77
  Signal Layer 2 w8: v1(-203,-930.19) -203,-928.12 v1@-200.59,-925.71 ; v1(-203,-758.19) -203,-757.11 -200,-754.11 v1(-200,-658.19) -38.28,-658.19 v1(-29.54,-649.46) -29.54,-579.14 -32.54,-576.14 v1(-32.54,-575.06) -32.54,-562.28 -66,-528.83 v1(-66,-523.19) ; v1@-202.23,-759.27 -202.23,-760.04 -200,-762.27 v1(-200,-812.69) -200,-817 -183.35,-833.65 -183.35,-897.78 -200.59,-915.02 v1@-200.59,-925.71 ; v1(-15.46,-714.63) -14.7,-715.39 -14.7,-730.32 v1(-0.54,-744.47) ; v1(156,-982.85) v1@156,-981.99 ; v1(208.92,-649.46) 128.68,-729.69 14.24,-729.69 v1(-0.54,-744.47) ; v1(223,-915.19) 223,-941.69 v1(183,-981.69) 182.7,-981.99 155.8,-981.99 12.09,-838.28 3.28,-838.28 v1(2.95,-837.95) ; v1(223,-840.05) 174.41,-791.46 40.79,-791.46 40.08,-792.16 13.96,-792.16 v1@2.95,-781.16 ; v1@-200.59,-925.71 -101.8,-925.71 -31.79,-855.69 v1(-31.79,-837.7) 2.7,-837.7 v1(2.95,-837.95) ; v1(-0.54,-744.47) 0.46,-745.47 v1(0.46,-778.66) v1@2.95,-781.16 ; v1(2.95,-837.95) v1@2.95,-781.16
  Signal Layer 1 w10: v1(279.37,-1018.62) 292.08,-1031.34 540.01,-1031.34 540.08,-1031.27 v1(540.5,-1031.27)
  Bottom Layer w10: v1(540.5,-1031.27) 540.5,-1017.02 D1.A@555,-1002.52
  other v1: 2.06,-808.56 -61.34,-618.88 -61.34,-573.49
VDD_BAT: C12.2 E1.65 U17.C2 | length 970.6
  Top Layer w6: C12.2@-127,-1005.5 -126.02,-1005.5 -117.2,-996.69 -117.2,-989.61 v1(-94,-966.4) -94,-932.97 U17.C2@-108.78,-918.19
  Signal Layer 1 w4: v1(-6,-1357.19) -4.47,-1358.72 -0.39,-1358.72 0.34,-1359.46 47,-1359.46 58.69,-1347.76 72.85,-1347.76 73.46,-1348.37 93.04,-1348.37 109.59,-1331.82 v1(109.59,-1331.69)
  Bottom Layer w4: v1(-94,-966.4) -92.47,-967.93 -92.47,-971.8 -77.8,-986.47 -76.98,-986.47 -63.51,-999.94 -63.51,-1045.11 -64.33,-1045.94 -64.33,-1092.86 -57.2,-1100 -57.2,-1100.55 -54.12,-1103.62 ; -51.05,-1106.69 -54.12,-1103.62 ; v1(-6,-1357.19) -40.43,-1322.76 -40.43,-1132.17 ; v1(109.59,-1331.69) 126.59,-1348.69 277.69,-1348.69 282.95,-1353.95 282.95,-1399.36 265.75,-1416.57 E1.65@265.75,-1459.65 ; -54.12,-1103.64 -40.43,-1117.33 -40.43,-1126.85 ; -40.43,-1132.17 -41.43,-1131.17 -41.43,-1127.85 -40.43,-1126.85 ; -40.43,-1132.17 -40.43,-1126.85
VMOD: C47.2 C48.2 C51.2 C56.2 C57.2 E1.2 E1.4 FB1.1 Q3.4 Q4.4 R6.1 R10.1 U11.52 U11.53 | length 520.2
  Top Layer w8: -388.52,-1335.32 -383.84,-1340 -380.84,-1337 -363.92,-1337 v1(-362,-1338.92) ; v3(-379.45,-220.31) -378.69,-219.55 -367.34,-219.55 R10.1@-365,-217.2 -365,-217.43 -362.11,-220.31 Q3.4@-332.48,-220.31 ; v1(-361.89,-1389.19) -354.33,-1396.75 E1.2@-354.33,-1449.8 ; E1.4@-334.65,-1449.8 v1(-334.65,-1389.19) ; Q4.4@-195.31,-437.52 -195.31,-430.63 -193.41,-428.72 -186.52,-428.72 -185,-427.2 R6.1@-160,-427.2 -160,-390.69 -166,-384.69 v1(-166,-384)
  Signal Layer 1 w8: v3(-379.45,-220.31) -378.39,-220.31 -308.71,-290 v1(-182,-290)
  other v1: -375.51,-1375.57 -348.27,-1375.57 -361.89,-1361.95 -334.65,-1361.95 -375.51,-1348.33 -348.27,-1347.96 -555,-675 -535,-675 -515,-675 -565,-655 -545,-655 -525,-655 -575,-635 -555,-635 -535,-635 -182,-384 -150,-384 -182,-310 -166,-310 -150,-310 -166,-290 -150,-290
VSIM: C55.2 U10.8 U11.43 | length 165.2
  Top Layer w6: U10.8@-339.43,-620.46 -339.43,-613.74 -329.08,-603.38 -315,-603.38 ; v1(-315,-637.46) -315,-603.38 ; C55.2@-276.5,-592.35 -304.66,-592.35 -315,-602.69 -315,-603.38
  Bottom Layer w6: U11.43@-359.77,-655.35 -358.51,-654.1 -331.64,-654.1 v1(-315,-637.46)
pads on no net: E1.67 F1.0 F2.0 U10.2 U10.4 U10.5 U10.9 U11.2 U11.4 U11.5 U11.6 U11.7 U11.11 U11.12 U11.13 U11.14 U11.16 U11.22 U11.23 U11.24 U11.25 U11.26 U11.28 U11.40 U11.41 U11.42 U11.51 U11.56 U11.57 U11.63 U11.64 U11.65 U11.66 U11.76 U11.77 U11.78 U11.83 U11.84 U11.85 U11.86 U11.87 U11.88 U11.92 U11.93 U11.94 U11.95 U11.96 U11.97 U11.98 U11.99 U17.A1 U17.A2 U17.A6 U17.A7 U17.A10 U17.A11 U17.A12 U17.B7 U17.B8 U17.B10 U17.B11 U17.C7 U17.C10 U17.D4 U17.D8 U17.D11 U17.D12 U17.E2 U17.E8 U17.E9 U17.E11 U17.E12 U17.F11 U17.G11 U17.H10 U17.H12 U17.J4 U17.J6 U17.J7 U17.J11 U17.K6 U17.K7 U17.K10 U17.K11

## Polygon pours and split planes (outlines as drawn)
GND on Signal Layer 1 "GND_L02_P025" (solid, remove dead copper, pour order 25): -590.55,-4.32 -590.55,-1354.71 -408.08,-1354.71 -388.4,-1374.4 -388.4,-1512.19 393.1,-1512.19 393.1,-1374.4 412.79,-1354.71 590.55,-1354.71 590.55,-4.32
VMOD on Signal Layer 1 "VMOD_L02_P013" (solid, remove dead copper, pour order 13): -331.28,-1408.19 -318.54,-1395.46 -318.54,-1321.46 -398.54,-1241.46 -398.54,-946.46 -398.54,-798.99 -94.26,-494.7 -94.26,-271.46 -94.26,-269.45 -200.55,-269.45 -269.79,-335 -269.79,-438.67 -324.39,-493.27 -478.84,-493.81 -590.55,-605.52 -590.55,-1358.27 -388.93,-1358.27 -383.54,-1363.65 -383.54,-1408.19
VDD on Signal Layer 1 "VDD_L02_P004" (solid, remove dead copper, pour order 4): 330,-1405 348.19,-1405 457,-1296.19 457,-1084 246.46,-873.46 246.46,-840.46 241.36,-835.36 55.84,-835.36 41.1,-850.09 21.46,-850.09 21.46,-816.46 21.46,-781.46 16.46,-776.46 16.46,-746.46 47.27,-715.64 227.34,-715.65 236.36,-706.62 236.36,-661.58 216.23,-641.46 61.46,-641.46 21.45,-681.46 21.46,-715.64 10.64,-726.46 -3.54,-726.46 -18.54,-711.46 -18.54,-602.54 -18.54,-519.46 -27.64,-510 -65.36,-510 -77.54,-523.14 -77.54,-595.46 -108.54,-626.46 -181.46,-626.46 -228.54,-673.54 -228.54,-706.43 -228.54,-825.96 -228.54,-916.94 -190.5,-954.99 -190.5,-970.93 -53.73,-1107.69 87.69,-1107.69 146.46,-1166.46 281.46,-1301.46 281.46,-1356.46
GND on Signal Layer 2 "GND_L03_P032" (solid, remove dead copper, pour order 32): -590.55,3.94 -590.55,-1358.27 -398.62,-1358.27 -390.75,-1366.14 -390.75,-1503.94 390.75,-1503.94 390.75,-1366.14 398.62,-1358.27 590.55,-1358.27 590.55,3.94
VDD on Signal Layer 2 "VDD_L03_P005" (solid, pour order 5): -220.15,-667.86 -220.15,-929.85 -210,-940 -95,-940 -30,-875 7.55,-875 22.81,-859.74 22.81,-832.61 40.79,-814.63 169.74,-814.63 203.15,-848.04 230.41,-848.04 237.04,-841.41 237.04,-810.76 209.58,-783.3 21.35,-783.3 14.24,-776.19 14.24,-751.34 25.58,-740 155.24,-740 227.4,-667.83 227.4,-652.97 209.44,-635 189.82,-635 129.82,-695 37.39,-695 -20.52,-755 -20.52,-790.96 -45.96,-790.96 -45.96,-699.37 -10.59,-663.99 -10.59,-544.41 -40,-515 -70,-515 -93.24,-538.24 -93.24,-593.99 -124.99,-625.73 -178.03,-625.73
GND on Top Layer "GND_L01_P027" (solid, remove dead copper, pour order 27): -590.55,3.94 -590.55,-1358.27 -398.62,-1358.27 -390.75,-1366.14 -390.75,-1400.19 390.75,-1400.19 390.75,-1366.14 398.62,-1358.27 590.55,-1358.27 590.55,3.94
GND on Bottom Layer "GND_L04_P031" (solid, remove dead copper, pour order 31): -590.55,3.94 -590.55,-1358.27 -398.62,-1358.27 -390.75,-1366.14 -390.75,-1405.51 390.75,-1405.51 390.75,-1366.14 398.62,-1358.27 590.55,-1358.27 590.55,3.94

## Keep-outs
Keep-Out Layer:
  lines w2: -590.55,0 -590.55,-1358.27 -410.43,-1358.27 cw(c-410.43,-1377.95) -390.75,-1377.95 -390.75,-1515.75 -126.97,-1515.75 -126.97,-1401.6 cw(c-103.35,-1401.57) -79.72,-1401.6 -79.72,-1515.75 390.75,-1515.75 390.75,-1377.95 cw(c410.43,-1377.95) 410.43,-1358.27 590.55,-1358.27 590.55,0
Mechanical 1:
  lines w3.94: -433.07,-1346.46 433.07,-1346.46

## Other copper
Top Layer:
  region net VMOD: -381.73,-1301.46 -509.8,-1301.46 -530,-1281.26 -530,-938.59 -490,-898.59 -490,-665 -530,-625 -580,-625 -583.41,-628.41 -583.41,-1351.13 -398.87,-1351.13 -380,-1370 -380,-1305
  region net VDD: -80,-525 -70,-515 -25,-515 -15,-525 -15,-570 -35.32,-590.32 -72,-590.32 -80,-582.31
  region net VMOD: -195,-395 -215,-375 -215,-280 -195,-260 -165,-260 -150,-245 -150,-215 -135,-200 -95,-200 -95,-350 -140,-395
  region net NetC23_2: -490,-1093.19 -470,-1073.19 -435,-1073.19 -385,-1123.19 -415,-1123.19 -415,-1118.19 -425,-1108.19 -475,-1108.19
  pour cut-out: 722,-636.64 747,-636.64 747,-651.64 722,-651.64
  region net VDD: 334.46,-1343.46 353.72,-1343.46 354.33,-1344.07 354.33,-1401.46 334.46,-1401.46
  region net NetC23_2: -410.43,-1118.19 -390,-1118.19 -335,-1173.19 -335,-1286.46 -376.73,-1286.46 -410.43,-1252.76
  region net VMOD: -393.54,-1313.27 -381.73,-1301.46 -345.43,-1301.46 -345.43,-1329.57 -318.54,-1356.46 -318.54,-1393.54 -335,-1410 -350,-1410 -383.54,-1376.46 -383.54,-1346.48 -393.54,-1336.48
  region net GND: -69.48,0 -118.36,0 -118.73,-39.37 -117.27,-57.9 -112.93,-75.98 -105.81,-93.16 -96.1,-109.01 -84.03,-123.14 -69.89,-135.22 -54.04,-144.93 -36.86,-152.05 -18.79,-156.39 -0.25,-157.85 18.28,-156.39 36.36,-152.05 53.53,-144.93 69.39,-135.22 83.52,-123.14 95.6,-109.01 105.31,-93.16 112.42,-75.98 116.76,-57.9 118.22,-39.37 117.86,0 68.98,0 67.65,-13.51 63.71,-26.49 57.31,-38.46 48.7,-48.95 38.21,-57.56 26.24,-63.96 13.25,-67.9 -0.25,-69.23 -13.76,-67.9 -26.75,-63.96 -38.71,-57.56 -49.21,-48.95 -57.82,-38.46 -64.21,-26.49 -68.15,-13.51
Signal Layer 2:
  pour cut-out: -140,-150 -443.23,-150 -466.85,-173.62 -466.85,-308.96 -431.85,-343.96 -326.04,-343.96 -325,-345 -325,-450 -505.87,-450 -570,-385.87 -570,-90 -520,-40 -140,-40
  pour cut-out: 154.57,-41.46 259.57,-41.46 259.57,-376.46 154.57,-376.46
Bottom Layer:
  region net RF_2: -387.66,-409.09 -387.66,-382.09 -379.27,-382.09 -379.27,-409.09
  region net NetC23_2: -410.43,-1172.76 -410.43,-1123.62 -385,-1098.19 -341.81,-1098.19 -337.38,-1102.62 -337.38,-1192.32 -348.25,-1203.19 -380,-1203.19
  region net RF_1_ANT: 194.57,-315.46 221.57,-315.46 221.57,-323.84 194.57,-323.84
  region net GND: -392.5,-461.37 -392.5,-425 -327.5,-425 -327.5,-461.37
  region net VDD: 334.46,-1343.46 353.72,-1343.46 353.72,-1381.98 334.46,-1381.98
  region net GND: 318.38,-314.71 237.27,-314.71 237.27,-376.46 318.38,-376.46
  region net GND: 97.91,-314.71 179.25,-314.71 179.25,-376.46 97.91,-376.46
  region net GND: -130.43,-311.46 -40.43,-311.46 -40.43,-376.46 -130.43,-376.46
  region net GND: -305.43,-311.46 -255.43,-311.46 -255.43,-376.46 -305.43,-376.46
  region net VMOD: -210.43,-271.46 -135.43,-271.46 -135.43,-371.46 -155.43,-391.46 -195.43,-391.46 -210.43,-376.46
  region net GND: 117.13,-7.87 117.13,0 69.88,0 69.88,-7.87
  region net GND: -119.09,-7.87 -119.09,0 -67.91,0 -67.91,-7.87
  pour cut-out: -151.34,-70 -279.52,-70 -279.52,-130 -151.34,-130
  pour cut-out: 242.13,-130.79 242.13,-40.68 175.2,-40.68 175.2,-130.79

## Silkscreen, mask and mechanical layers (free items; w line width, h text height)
Top Overlay:
  text "H" at 158.29,-203.62 h350
  text "J" at 168,-220 h100
  text "imp006-m2 rev2.0 / 20210330" at 25.25,-1375 h55
Bottom Overlay:
  text "GPS" at -287.18,-45.2 h40
  text "LTE" at 359,-45.2 h40
  text "netlight" at 565,-800 h40 r90
Top Solder:
  region: -69.15,0 -118.36,0 -118.73,-39.37 -117.27,-57.9 -112.93,-75.98 -105.81,-93.16 -96.1,-109.01 -84.03,-123.14 -69.89,-135.22 -54.04,-144.93 -36.86,-152.05 -18.79,-156.39 -0.25,-157.85 18.28,-156.39 36.36,-152.05 53.53,-144.93 69.39,-135.22 83.52,-123.14 95.6,-109.01 105.31,-93.16 112.42,-75.98 116.76,-57.9 118.22,-39.37 117.86,-39.37 117.86,0 68.98,0 67.65,-13.51 63.71,-26.49 57.31,-38.46 48.7,-48.95 38.21,-57.56 26.24,-63.96 13.25,-67.9 -0.25,-69.23 -13.76,-67.9 -26.75,-63.96 -38.71,-57.56 -49.21,-48.95 -57.82,-38.46 -64.21,-26.49 -68.15,-13.51 -69.48,0 -69.15,0
Bottom Solder:
  lines w39.37: -88.58,0 ccw(c0,0) 88.58,0
  text "M" at 317,-146 h110
  text "G" at 447,-165 h220
Mechanical 1:
  lines w3.94: -528.54,-136.94 528.54,-137.53 ; -528.54,11.81 528.54,11.81
Mechanical 13:
  drawing of 525 lines, arcs and shapes, not listed
  text "Layer" at 2950.53,3366.86 h60
  text "Name" at 3360.45,3366.86 h60
  text "Material" at 4300.19,3366.86 h60
  text "Thickness" at 5159.95,3366.86 h60
  text "Constant" at 5809.79,3366.86 h60
  text "Board Layer Stack" at 6379.65,3366.86 h60
  text "Top Overlay" at 3360.45,3246.86 h60
  text "Top Solder" at 3360.45,3126.86 h60
  text "Solder Resist" at 4300.19,3126.86 h60
  text "0.40mil" at 5159.95,3126.86 h60
  text "3.5" at 5809.79,3126.86 h60
  text "1" at 2950.53,3006.86 h60
  text "Top Layer" at 3360.45,3006.86 h60
  text "1.40mil" at 5159.95,3006.86 h60
  text "Dielectric 1" at 3360.45,2886.86 h60
  text "FR-4" at 4300.19,2886.86 h60
  text "2.76mil" at 5159.95,2886.86 h60
  text "3.86" at 5809.79,2886.86 h60
  text "2" at 2950.53,2766.86 h60
  text "Signal Layer 1" at 3360.45,2766.86 h60
  text "0.70mil" at 5159.95,2766.86 h60
  text "Dielectric 2" at 3360.45,2646.86 h60
  text "FR-4" at 4300.19,2646.86 h60
  text "22.05mil" at 5159.95,2646.86 h60
  text "4.27" at 5809.79,2646.86 h60
  text "3" at 2950.53,2526.86 h60
  text "Signal Layer 2" at 3360.45,2526.86 h60
  text "0.70mil" at 5159.95,2526.86 h60
  text "Dielectric 3" at 3360.45,2406.86 h60
  text "FR-4" at 4300.19,2406.86 h60
  text "2.76mil" at 5159.95,2406.86 h60
  text "3.86" at 5809.79,2406.86 h60
  text "4" at 2950.53,2286.86 h60
  text "Bottom Layer" at 3360.45,2286.86 h60
  text "1.40mil" at 5159.95,2286.86 h60
  text "Bottom Solder" at 3360.45,2166.86 h60
  text "Solder Resist" at 4300.19,2166.86 h60
  text "0.40mil" at 5159.95,2166.86 h60
  text "3.5" at 5809.79,2166.86 h60
  text "Bottom Overlay" at 3360.45,2046.86 h60
Mechanical 16:
  the board outline again, w3.94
